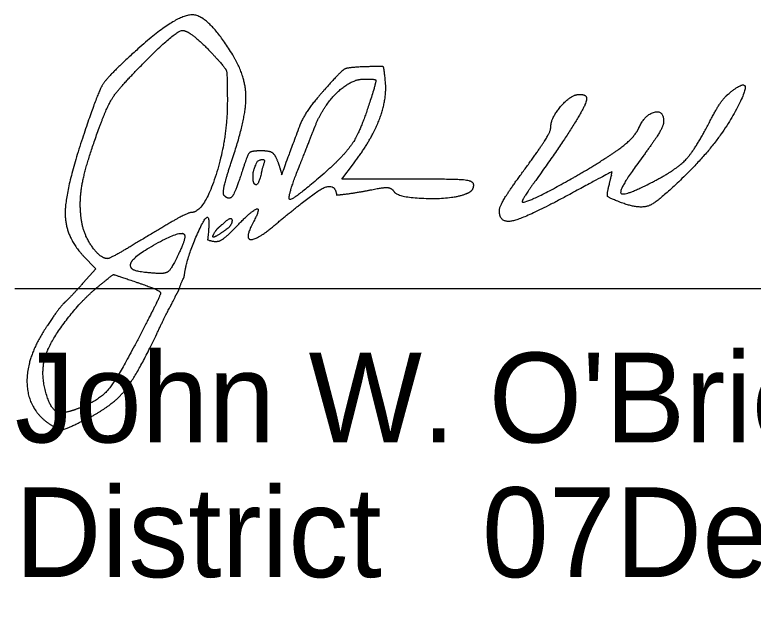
# Model space of a CAD drawing. Extents: x 0 to 34, y 0 to 22.
# Drawn here: x 24.528 to 25.679, y 8.434 to 9.353 of the extents above; entities that cross this region are included whole.
import ezdxf

# ---------------------------------------------------------------- set-up
doc = ezdxf.new("R2010")
doc.units = 0
doc.layers.add('SH_Data', color=7, linetype='Continuous')
doc.layers.add('SH_Text', color=7, linetype='Continuous')

msp = doc.modelspace()

# ---------------------------------------------------------------- linework, layer by layer
at = {"layer": 'SH_Data'}
msp.add_line((24.5279, 8.9262), (28.0279, 8.9262), dxfattribs=at)
at = {"layer": 'SH_Text'}
for points in [[(25.1404, 9.0966), (25.0375, 9.0966), (25.0558, 9.1206)], [(24.6346, 8.9772), (24.654, 8.9566), (24.6346, 8.9348)]]:
    msp.add_lwpolyline(points, dxfattribs=at)
for points in [[(24.8676, 9.2902), (24.8304, 9.3511), (24.781, 9.3542), (24.7199, 9.2995)], [(24.7219, 9.2706), (24.7758, 9.3259), (24.8, 9.3304), (24.836, 9.2918)], [(24.7199, 9.2995), (24.6737, 9.2582), (24.656, 9.2292), (24.6319, 9.1557)], [(24.836, 9.2918), (24.8564, 9.2699), (24.8592, 9.261), (24.8592, 9.2177)], [(24.8663, 9.1257), (24.888, 9.1897), (24.8885, 9.2559), (24.8676, 9.2902)], [(24.6595, 9.1766), (24.672, 9.2107), (24.69, 9.2379), (24.7219, 9.2706)], [(25.0723, 9.2716), (25.0465, 9.2708), (25.0363, 9.2649), (25.0106, 9.2359)], [(25.1056, 9.2482), (25.1034, 9.271), (25.1012, 9.2725), (25.0723, 9.2716)], [(24.9955, 9.1777), (25.008, 9.2099), (25.052, 9.2526), (25.0726, 9.2526)], [(25.0558, 9.1206), (25.0834, 9.1568), (25.1083, 9.2207), (25.1056, 9.2482)], [(25.0726, 9.2526), (25.0893, 9.2526), (25.0915, 9.2499), (25.0869, 9.2346)], [(25.64, 9.2292), (25.6828, 9.2648), (25.629, 9.1584), (25.5787, 9.1082)], [(25.0106, 9.2359), (24.9936, 9.2167), (24.976, 9.1911), (24.9715, 9.1788)], [(25.0869, 9.2346), (25.0699, 9.1788), (25.0454, 9.1369), (25.013, 9.1083)], [(25.4192, 9.2214), (25.4192, 9.2136), (25.3786, 9.1487), (25.3398, 9.0946)], [(25.3632, 9.1766), (25.3632, 9.1916), (25.3949, 9.2286), (25.4078, 9.2286)], [(25.4078, 9.2286), (25.4141, 9.2286), (25.4192, 9.2254), (25.4192, 9.2214)], [(25.611, 9.1861), (25.6205, 9.2045), (25.6335, 9.2239), (25.64, 9.2292)], [(24.8592, 9.2177), (24.8592, 9.1578), (24.8225, 9.0446), (24.803, 9.0446)], [(25.5007, 9.1766), (25.5102, 9.1974), (25.5392, 9.2045), (25.5392, 9.1861)], [(25.5392, 9.1861), (25.5392, 9.1802), (25.5248, 9.1562), (25.5072, 9.1325)], [(25.5203, 9.0912), (25.5584, 9.1108), (25.5884, 9.1422), (25.611, 9.1861)], [(24.6328, 9.0272), (24.6272, 9.0565), (24.6384, 9.1192), (24.6595, 9.1766)], [(24.9715, 9.1788), (24.9427, 9.1013), (24.9449, 9.105), (24.9381, 9.1235)], [(24.9722, 9.1186), (24.9814, 9.1417), (24.9919, 9.1683), (24.9955, 9.1777)], [(25.3232, 9.1126), (25.3452, 9.1424), (25.3632, 9.1712), (25.3632, 9.1766)], [(25.4494, 9.1297), (25.4726, 9.1445), (25.4957, 9.1656), (25.5007, 9.1766)], [(24.6319, 9.1557), (24.6059, 9.0764), (24.607, 9.0067), (24.6346, 8.9772)], [(24.9121, 9.1406), (24.8965, 9.1406), (24.8905, 9.1345), (24.8829, 9.1106)], [(24.9381, 9.1235), (24.934, 9.1346), (24.9249, 9.1406), (24.9121, 9.1406)], [(24.9062, 9.1246), (24.9197, 9.1312), (24.913, 9.1121), (24.9118, 9.1043)], [(25.3196, 9.0606), (25.3278, 9.0606), (25.4081, 9.1033), (25.4494, 9.1297)], [(25.5072, 9.1325), (25.47, 9.0827), (25.4747, 9.0678), (25.5203, 9.0912)], [(24.8545, 9.0707), (24.8517, 9.0735), (24.8571, 9.0982), (24.8663, 9.1257)], [(24.8992, 9.1001), (24.8992, 9.1043), (24.8998, 9.1099), (24.9062, 9.1246)], [(25.013, 9.1083), (24.962, 9.0635), (24.9513, 9.0662), (24.9722, 9.1186)], [(24.8829, 9.1106), (24.8723, 9.0773), (24.8621, 9.0631), (24.8545, 9.0707)], [(24.9118, 9.1043), (24.9078, 9.087), (24.8992, 9.0886), (24.8992, 9.1001)], [(25.2832, 9.0475), (25.2832, 9.0535), (25.3012, 9.0828), (25.3232, 9.1126)], [(25.4546, 9.0889), (25.4595, 9.1084), (25.4579, 9.108), (25.3928, 9.0728)], [(25.5787, 9.1082), (25.5329, 9.0624), (25.5023, 9.0488), (25.4719, 9.0604)], [(25.2432, 9.0875), (25.2432, 9.0938), (25.2122, 9.0966), (25.1404, 9.0966)], [(25.3398, 9.0946), (25.3264, 9.0759), (25.3173, 9.0606), (25.3196, 9.0606)], [(24.9324, 9.0243), (24.9663, 9.0529), (25.0264, 9.0971), (25.0295, 9.0718)], [(25.0843, 9.0801), (25.1028, 9.0839), (25.1154, 9.0829), (25.1188, 9.0773)], [(25.2306, 9.0735), (25.2375, 9.0761), (25.2432, 9.0824), (25.2432, 9.0875)], [(25.4719, 9.0604), (25.4533, 9.0674), (25.4504, 9.0722), (25.4546, 9.0889)], [(25.0295, 9.0718), (25.0437, 9.0731), (25.0683, 9.0769), (25.0843, 9.0801)], [(25.1188, 9.0773), (25.1245, 9.0681), (25.209, 9.0652), (25.2306, 9.0735)], [(25.3928, 9.0728), (25.3258, 9.0365), (25.2832, 9.0267), (25.2832, 9.0475)], [(24.8708, 9.0202), (24.8973, 9.0478), (24.9119, 9.0524), (24.8995, 9.0291)], [(24.803, 9.0446), (24.7991, 9.0446), (24.7691, 9.0284), (24.7365, 9.0086)], [(24.792, 8.9444), (24.7951, 8.9734), (24.8361, 9.0628), (24.8283, 9.0021)], [(24.8544, 9.0286), (24.8647, 9.0389), (24.8678, 9.028), (24.8603, 9.02)], [(24.6725, 8.9726), (24.6619, 8.9726), (24.6366, 9.0074), (24.6328, 9.0272)], [(24.841, 9.0157), (24.8436, 9.0195), (24.8482, 9.0235), (24.8544, 9.0286)], [(24.8995, 9.0291), (24.886, 9.0038), (24.9047, 9.0011), (24.9324, 9.0243)], [(24.8283, 9.0021), (24.8419, 8.9972), (24.8569, 9.0056), (24.8708, 9.0202)], [(24.8603, 9.02), (24.8459, 9.0093), (24.833, 9.0039), (24.841, 9.0157)], [(24.7365, 9.0086), (24.7039, 8.9888), (24.6751, 8.9726), (24.6725, 8.9726)], [(24.709, 8.9658), (24.7125, 8.9763), (24.786, 9.0165), (24.7916, 9.0109)], [(24.7916, 9.0109), (24.794, 9.0085), (24.7897, 8.9935), (24.7821, 8.9776)], [(24.7821, 8.9776), (24.7724, 8.9573), (24.7633, 8.9489), (24.7518, 8.9495)], [(24.7518, 8.9495), (24.7233, 8.9511), (24.7062, 8.9576), (24.709, 8.9658)], [(24.6594, 8.9304), (24.6806, 8.9477), (24.6826, 8.9479), (24.7183, 8.9357)], [(24.7792, 8.9159), (24.7828, 8.921), (24.7859, 8.9315), (24.792, 8.9444)], [(24.6346, 8.9348), (24.624, 8.9229), (24.6112, 8.9094), (24.6063, 8.9048)], [(24.7183, 8.9357), (24.7386, 8.9288), (24.7552, 8.9213), (24.7552, 8.9191)], [(24.5745, 8.8165), (24.5802, 8.8392), (24.631, 8.9073), (24.6594, 8.9304)], [(24.7552, 8.9191), (24.7552, 8.9169), (24.7405, 8.8868), (24.7226, 8.8522)], [(24.7491, 8.8553), (24.7618, 8.8822), (24.7762, 8.909), (24.7792, 8.9159)], [(24.6063, 8.9048), (24.6013, 8.9003), (24.5878, 8.8823), (24.5763, 8.8648)], [(24.5763, 8.8648), (24.5453, 8.8179), (24.5487, 8.7373), (24.5824, 8.7147)], [(24.7226, 8.8522), (24.688, 8.7858), (24.6592, 8.7513), (24.6287, 8.7397)], [(24.6426, 8.7243), (24.6803, 8.7435), (24.7185, 8.7905), (24.7491, 8.8553)], [(24.599, 8.7326), (24.5855, 8.7326), (24.5682, 8.7916), (24.5745, 8.8165)], [(24.6287, 8.7397), (24.6185, 8.7358), (24.6052, 8.7326), (24.599, 8.7326)], [(24.5824, 8.7147), (24.5964, 8.7054), (24.6097, 8.7075), (24.6426, 8.7243)]]:
    msp.add_open_spline(points, degree=2, dxfattribs=at)

# ---------------------------------------------------------------- texts
for s, p in [("John W. O'Brien", (24.5279, 8.6862)), ('District       Deputy Director', (24.5279, 8.4762)), ('              07', (24.5279, 8.4762))]:
    msp.add_text(s, height=0.14, dxfattribs=at).set_placement(p)

doc.saveas('drawing.dxf')
